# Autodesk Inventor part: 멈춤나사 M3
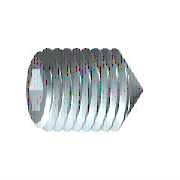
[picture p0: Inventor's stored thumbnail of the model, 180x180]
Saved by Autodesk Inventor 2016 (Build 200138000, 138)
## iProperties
IsCustomPart: 1
Created: 2012-02
Part Number: 멈춤나사 M3
Material: 강철, 연강
Description: 6각 소켓 머리 없는 멈춤 나사
Document SubType Name: Modeling
Standard: KS B 1028
Designer: test
Standards Organization: KS
Language: ko-KR
Size Designation: 원추점 M3x8
Categories: <MemberInstance><Categories><Category DisplayName="조임쇠" InternalName="e4da775c-781d-43d5-af7c-5136215cf5a6" Mnemonic="FSTN"><Category DisplayName="볼트" InternalN
Density: 1 g/cm^3
Appearance: 강철
Author: test
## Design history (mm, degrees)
sketch "스케치1"
  geometry: L1 (0, 0)-(5.5, 0); L2 (8, 0.866)-(8, 1.5); L3 (8, 1.5)-(0, 1.5); L4 (8, 0.866)-(6, 0.866); L5 (6, 0.866)-(5.5, 0); L6 (0, -0.3)-(0, 1.8) reference; L7 (0, 1.5)-(0, 0)
  constraints: 13 end point, 3 parallel, 1 collinear, 1 perpendicular, 1 point on line
  dimensions: "d0" = 2 distance of L2.start L4.end (= INTI); "d1" = 60 deg angle of L5 L1; "d2" = 3 diameter of L3 L1 (= NND); "d3" = 1.73205 diameter of L4 L1 (= 1.1547 x SW); "d5" = 8 distance from line of L2 L3.end (= NLG)
revolve "본체" sketch "스케치1" stored, may be unused: angle "d6" = 90 deg
sketch "스케치2"
  geometry: L1 (-0.433, 0.75)-(0.433, 0.75); L2 (0.433, 0.75)-(0.866, 0); L3 (0.866, 0)-(0.433, -0.75); L4 (0.433, -0.75)-(-0.433, -0.75); L5 (-0.433, -0.75)-(-0.866, 0); L6 (-0.866, 0)-(-0.433, 0.75); 3 further points
  constraints: 12 end point, 1 coincident, 1 horizontal, 13 other
extrude "슬롯" join sketch "스케치2" taper "d7" = 0 deg; stored distance "d21" = 10
workaxis "Work Axis1"
workplane "Work Plane1"
sketch "스케치4"
  geometry: L1 (0, 0.15)-(-1.35, 1.5) reference; L2 (0, -0.15)-(-1.35, -1.5) reference; L3 (-1.35, -1.5)-(0.15, 0); L4 (-1.35, 1.5)-(0.15, 0); 2 further points
  constraints: 4 end point, 1 coincident, 1 collinear, 1 horizontal alignment
body "Solid1"
feature "스레드" dims "d12" = 8 (= NLG), "d13" = 0
chamfer "모따기1" distance "d8" = 1.35 (computed from NND, SPD, FAWI); stored, may be unused: angle "d9" = 45 deg (= FAWI), second distance "d34" = 1.35 (computed from NND, SPD, FAWI)
chamfer "모따기2" distance "d10" = 0.30673 (= -0.5 x GD1 + 0.5 x NND); stored, may be unused: angle "d11" = 45 deg (= FAWI), second distance "d35" = 0.30673 (= -0.5 x GD1 + 0.5 x NND)
other parameters: "NND" = 3 [user parameter; used in 5 equation terms], "NLG" = 8 [user parameter; used in 2 equation terms], "INTI" = 2 [user parameter; used in 1 equation term], "FAWI" = 45 deg [user parameter; used in 4 equation terms], "SW" = 1.5 [user parameter; used in 2 equation terms], "GD1" = 2.38655 (= THREADDIA - 1.2269 x PTC) [user parameter; used in 2 equation terms], "d4" = 0, "FAWI1" = 45 deg [user parameter], "SPD" = 0.3 [user parameter; used in 2 equation terms], "d36" = 0, "d37" = 0, "GUL" = 0.30673 (= 0.61345 x PTC) [user parameter], "TOA" = 30 deg [user parameter], "THREADDIA" = 3 [user parameter; used in 1 equation term], "PTC" = 0.5 [user parameter; used in 4 equation terms], "GAL" = 0.30673 (= 0.61345 x PTC) [user parameter], "E0" = 1.7325 (= 1.155 x SW) [user parameter]
